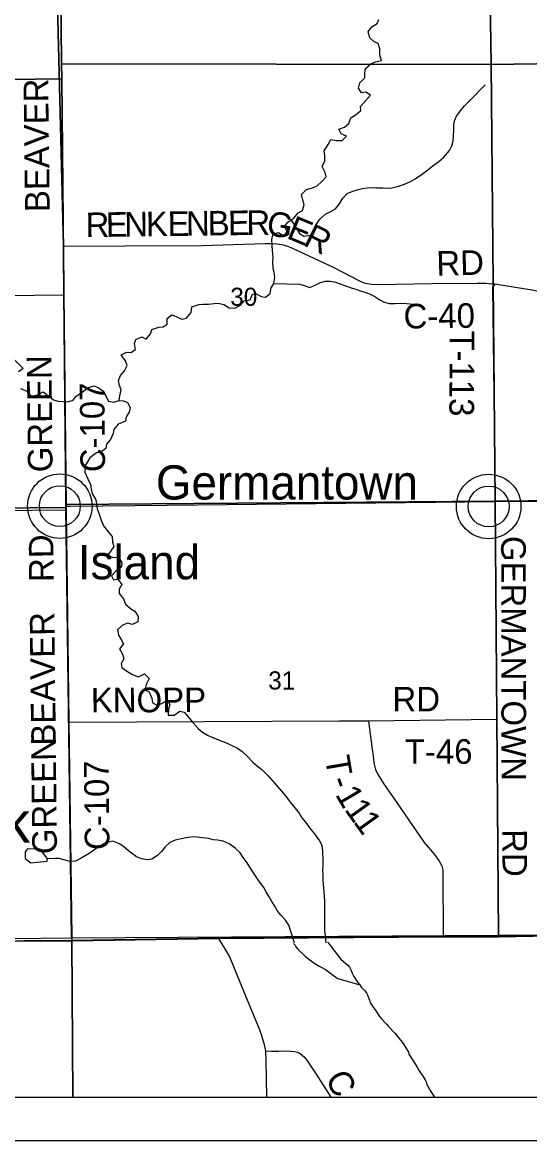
# Model space of a CAD drawing. Extents: x 0 to 36.9, y 0 to 22.
# Drawn here: x 4.148 to 5.318, y 14 to 16.582 of the extents above; entities that cross this region are included whole.
import ezdxf

# ---------------------------------------------------------------- set-up
doc = ezdxf.new("R2010")
doc.units = 0
for name, color, linetype in [('GM_X_County_Road', 7, 'Continuous'), ('GM_X_County_Road_Text', 7, 'Continuous'), ('GM_X_Minor_Lake', 7, 'Continuous'), ('GM_X_Minor_Lake_Text', 7, 'Continuous'), ('GM_X_Minor_River', 7, 'Continuous'), ('GM_X_Rail_Line', 7, 'Continuous'), ('GM_X_Section', 7, 'Continuous'), ('GM_X_Section_Text', 7, 'Continuous'), ('GM_X_State_Route', 7, 'Continuous'), ('GM_X_Township_Road', 7, 'Continuous'), ('GM_X_Township_Road_Text', 7, 'Continuous'), ('GM_X_Unincorporated', 7, 'Continuous'), ('GM_X_Unincorporated_Location', 7, 'Continuous'), ('GM_X_Unincorporated_Text', 7, 'Continuous'), ('SH_Cut_Line', 7, 'Continuous'), ('SH_Data', 7, 'Continuous')]:
    doc.layers.add(name, color=color, linetype=linetype)

msp = doc.modelspace()

# ---------------------------------------------------------------- linework, layer by layer
at = {"layer": 'GM_X_County_Road'}
for p, q in [((3.2939, 15.4488), (4.2488, 15.4562)), ((4.2488, 15.4651), (4.2587, 15.4652)), ((4.2488, 15.4562), (4.2488, 15.4651)), ((4.2552, 14.9656), (4.2488, 15.4562))]:
    msp.add_line(p, q, dxfattribs=at)
for points in [[(4.2488, 15.4651), (4.2434, 15.9526), (4.243, 16.0644), (4.2239, 16.8055), (4.2216, 17.4415)], [(5.2175, 15.9787), (5.197, 15.9789), (5.0925, 15.9784), (4.9679, 15.9763), (4.9529, 15.977), (4.9441, 15.9779), (4.9361, 15.9801), (4.9264, 15.9841), (4.8658, 16.0156), (4.776, 16.0576), (4.7622, 16.0637), (4.7526, 16.0667), (4.7461, 16.0686), (4.7358, 16.0701), (4.7243, 16.0705), (4.7077, 16.0705), (4.5615, 16.0663), (4.3849, 16.0655), (4.243, 16.0644)], [(5.3825, 15.9549), (5.3493, 15.9585), (5.3236, 15.9637), (5.2563, 15.9747), (5.2373, 15.9775), (5.2243, 15.9786), (5.2175, 15.9787)], [(4.2587, 15.4652), (4.4807, 15.4671), (5.2386, 15.4759), (5.5595, 15.4781), (5.5699, 15.4782), (5.5803, 15.4783), (6.0155, 15.4812)], [(4.2622, 14.4614), (4.2621, 14.4708), (4.2552, 14.9656)]]:
    msp.add_lwpolyline(points, dxfattribs=at)
at = {"layer": 'GM_X_Minor_Lake'}
for points in [[(4.1889, 14.6729), (4.1592, 14.6736), (4.1544, 14.667), (4.1539, 14.6511), (4.1669, 14.6411), (4.1817, 14.6428), (4.2049, 14.6451)], [(4.2049, 14.6451), (4.2055, 14.6476), (4.204, 14.6528), (4.1889, 14.6729)]]:
    msp.add_lwpolyline(points, dxfattribs=at)
at = {"layer": 'GM_X_Minor_River'}
for points in [[(4.9626, 16.4908), (4.9759, 16.4937), (4.9726, 16.5069), (4.9724, 16.5206), (4.9687, 16.5331), (4.9591, 16.5371), (4.9495, 16.546), (4.9458, 16.5604), (4.9536, 16.5719), (4.9664, 16.579), (4.97, 16.5889)], [(4.3707, 15.7089), (4.3728, 15.7195), (4.3759, 15.7336), (4.3716, 15.7438), (4.3695, 15.7548), (4.3738, 15.7662), (4.3831, 15.777), (4.3894, 15.7897), (4.3854, 15.8002), (4.3756, 15.8145), (4.3877, 15.8208), (4.3976, 15.8198), (4.4084, 15.8265), (4.4067, 15.8401), (4.4092, 15.85), (4.4231, 15.8556), (4.4331, 15.8508), (4.4431, 15.8624), (4.4463, 15.8731), (4.4622, 15.8783), (4.4721, 15.8788), (4.4818, 15.8851), (4.4816, 15.8984), (4.4928, 15.9065), (4.5024, 15.9025), (4.5154, 15.8967), (4.526, 15.8988), (4.5368, 15.9119), (4.5388, 15.9248), (4.5547, 15.9308), (4.5653, 15.9314), (4.5767, 15.9316), (4.5899, 15.9326), (4.5994, 15.9335), (4.6124, 15.9303), (4.6247, 15.9225), (4.6376, 15.9224), (4.6511, 15.9287), (4.6597, 15.9387), (4.6729, 15.9416), (4.6784, 15.9546), (4.6879, 15.9552), (4.6982, 15.9489), (4.7089, 15.9472), (4.7194, 15.9557), (4.7214, 15.9691), (4.7277, 15.979), (4.7301, 15.9928), (4.7284, 16.0045), (4.7263, 16.0143), (4.7253, 16.0291), (4.7262, 16.0401), (4.7248, 16.0553), (4.7238, 16.0671), (4.7232, 16.0803), (4.726, 16.0933), (4.7385, 16.0969), (4.7519, 16.0884), (4.7586, 16.0992), (4.7523, 16.1108), (4.7601, 16.1208), (4.7736, 16.1298), (4.784, 16.1425), (4.7942, 16.1476), (4.7977, 16.1606), (4.7937, 16.1742), (4.792, 16.1844), (4.8028, 16.196), (4.8171, 16.2001), (4.8281, 16.2044), (4.8393, 16.2149), (4.8482, 16.2249), (4.8465, 16.2355), (4.8394, 16.2491), (4.8453, 16.2621), (4.8458, 16.2746), (4.8441, 16.2852), (4.8533, 16.3002), (4.8592, 16.3113), (4.8717, 16.3092), (4.8858, 16.3091), (4.8951, 16.3195), (4.8832, 16.3243), (4.8777, 16.3352), (4.8909, 16.3403), (4.901, 16.3485), (4.9057, 16.3615), (4.9174, 16.3693), (4.9282, 16.3782), (4.9277, 16.3877), (4.9392, 16.4008), (4.9511, 16.4139), (4.94, 16.4206), (4.9301, 16.4189), (4.9231, 16.4298), (4.9263, 16.442), (4.9379, 16.4536), (4.938, 16.4646), (4.939, 16.4752), (4.9513, 16.4861), (4.9626, 16.4908)], [(4.7679, 16.1261), (4.7868, 16.0944), (4.7971, 16.0881), (4.813, 16.0907), (4.8193, 16.1006), (4.8255, 16.1152), (4.8344, 16.1282), (4.8478, 16.1395), (4.8576, 16.1442), (4.8697, 16.1513), (4.8793, 16.1632), (4.8867, 16.1759), (4.8971, 16.1867), (4.9099, 16.1922), (4.9201, 16.1951), (4.9326, 16.1983), (4.9428, 16.2), (4.9527, 16.201), (4.9633, 16.2), (4.9789, 16.1995), (4.9892, 16.1993), (4.9998, 16.1999), (5.0157, 16.2036), (5.0289, 16.2084), (5.0432, 16.2147), (5.0541, 16.2206), (5.071, 16.2319), (5.0829, 16.2413), (5.0953, 16.2517), (5.1084, 16.2607), (5.1193, 16.2696), (5.133, 16.2858), (5.1385, 16.2965), (5.1414, 16.3084), (5.1423, 16.3201), (5.1428, 16.3331), (5.1434, 16.3445), (5.1447, 16.3544), (5.1494, 16.3651), (5.1602, 16.3797), (5.168, 16.3893), (5.1814, 16.4028), (5.193, 16.4144), (5.2042, 16.426), (5.2153, 16.438)], [(4.7277, 15.979), (4.7877, 15.9775), (4.8003, 15.9735), (4.811, 15.9699), (4.8246, 15.9758), (4.8351, 15.981), (4.8472, 15.9842), (4.8578, 15.9844), (4.87, 15.982), (4.8811, 15.978), (4.893, 15.9736), (4.9063, 15.9689), (4.9167, 15.9657), (4.927, 15.9621), (4.938, 15.9589), (4.9503, 15.9542), (4.961, 15.9487), (4.9725, 15.9413), (4.9825, 15.9361), (4.9936, 15.9329), (5.008, 15.9332), (5.0228, 15.9338), (5.0338, 15.9325), (5.0494, 15.9309)], [(4.1295, 15.8031), (4.1491, 15.7831), (4.1386, 15.775)], [(4.1435, 15.7367), (4.1577, 15.7305), (4.1697, 15.7182), (4.1825, 15.7222), (4.1957, 15.7285), (4.208, 15.7193), (4.2195, 15.7107), (4.2302, 15.7075), (4.2416, 15.7062), (4.2515, 15.7056), (4.2651, 15.7093), (4.2714, 15.7189), (4.2849, 15.7275), (4.2976, 15.7383), (4.3124, 15.7424), (4.3227, 15.7388), (4.3354, 15.7299), (4.3397, 15.7201), (4.346, 15.7077), (4.3586, 15.7052), (4.3707, 15.7089), (4.3806, 15.7079), (4.3905, 15.7043), (4.3964, 15.693), (4.394, 15.682), (4.3873, 15.6708), (4.3852, 15.6609), (4.369, 15.6546), (4.359, 15.6422), (4.3569, 15.6323), (4.351, 15.6189), (4.3417, 15.6081), (4.3404, 15.5979), (4.3284, 15.5893), (4.3186, 15.588), (4.3036, 15.5767), (4.2977, 15.5671), (4.2918, 15.5571), (4.292, 15.5435), (4.2987, 15.528), (4.3047, 15.5149), (4.3064, 15.5043), (4.3088, 15.4941), (4.3171, 15.4798), (4.3184, 15.4696), (4.3205, 15.459), (4.3257, 15.4443), (4.3293, 15.4329), (4.3345, 15.4194), (4.3461, 15.4048), (4.355, 15.3947), (4.3557, 15.3814), (4.3589, 15.3716), (4.3448, 15.3516), (4.3571, 15.3461), (4.3703, 15.3475), (4.3774, 15.3351), (4.3764, 15.3248), (4.3637, 15.3155), (4.3529, 15.3043), (4.358, 15.2945), (4.3678, 15.2966), (4.3772, 15.2839), (4.3709, 15.2731), (4.3707, 15.2636), (4.3812, 15.2509), (4.3859, 15.2388), (4.3971, 15.2284), (4.4071, 15.2221), (4.4149, 15.2101), (4.4144, 15.198), (4.402, 15.1917), (4.3905, 15.1949), (4.3781, 15.1897), (4.3672, 15.1793), (4.3694, 15.1672), (4.3756, 15.157), (4.3807, 15.1469), (4.3715, 15.1353), (4.3789, 15.1233), (4.3821, 15.1124), (4.3758, 15.102), (4.3775, 15.0922), (4.3899, 15.0833), (4.4014, 15.0759), (4.4155, 15.0705), (4.4294, 15.0775), (4.4403, 15.0671), (4.4329, 15.0533), (4.4305, 15.0411), (4.4404, 15.036), (4.446, 15.0217), (4.4481, 15.0107), (4.46, 15.0048), (4.4705, 15.0099), (4.4822, 15.017)], [(4.4822, 15.017), (4.4877, 15.0068), (4.4848, 14.9962), (4.4843, 14.9821), (4.498, 14.9824), (4.5111, 14.9913), (4.521, 14.9892), (4.5299, 14.9784), (4.542, 14.9645), (4.5536, 14.9518), (4.5632, 14.9433), (4.5751, 14.9359), (4.5847, 14.9315), (4.6099, 14.9213), (4.6199, 14.9177), (4.6295, 14.913), (4.644, 14.9064), (4.6548, 14.8986), (4.6671, 14.8871), (4.6791, 14.8736), (4.6899, 14.8643), (4.7003, 14.8569), (4.715, 14.8424), (4.7255, 14.83), (4.736, 14.8173), (4.7456, 14.8068), (4.758, 14.7923), (4.7651, 14.7821), (4.7728, 14.7724), (4.7864, 14.7563), (4.7927, 14.7454), (4.8012, 14.735), (4.8098, 14.7222), (4.8214, 14.708), (4.8331, 14.6923), (4.8382, 14.6825), (4.8404, 14.6692), (4.8408, 14.6461), (4.8406, 14.6362), (4.8404, 14.6244), (4.8406, 14.6134), (4.8412, 14.6021), (4.8414, 14.5918), (4.8428, 14.5755), (4.8438, 14.5634), (4.8444, 14.552), (4.8446, 14.538), (4.8444, 14.5281), (4.8448, 14.5061), (4.8446, 14.4951), (4.8444, 14.4852), (4.8476, 14.4565)], [(4.7755, 14.4567), (4.7626, 14.4974), (4.7544, 14.5087), (4.7439, 14.5202), (4.7358, 14.5311), (4.7303, 14.5413), (4.7232, 14.5525), (4.717, 14.5627), (4.7103, 14.5743), (4.7044, 14.5841), (4.6951, 14.5976), (4.6869, 14.6092), (4.6791, 14.6204), (4.6724, 14.6313), (4.6666, 14.6411), (4.6572, 14.6534), (4.6498, 14.6647), (4.6386, 14.6751), (4.6248, 14.6851), (4.611, 14.6913), (4.5981, 14.6934), (4.5878, 14.6947), (4.5767, 14.6972), (4.563, 14.6992), (4.5512, 14.7009), (4.5417, 14.7011), (4.5315, 14.7002), (4.5209, 14.6985), (4.5111, 14.696), (4.5005, 14.6935), (4.488, 14.6884), (4.4768, 14.6783), (4.4687, 14.6679), (4.4593, 14.6583), (4.4462, 14.6501), (4.4352, 14.6487), (4.4226, 14.6508), (4.4108, 14.6555), (4.3965, 14.6659), (4.3823, 14.6774), (4.3719, 14.6852), (4.3562, 14.6914), (4.3403, 14.6877), (4.3306, 14.6822), (4.3204, 14.6759), (4.3084, 14.6674), (4.2979, 14.6603), (4.2836, 14.6525), (4.2705, 14.6454), (4.2568, 14.6441), (4.2461, 14.6473), (4.2328, 14.6516), (4.2233, 14.6514), (4.2047, 14.6503)], [(4.7734, 14.4555), (4.7769, 14.4516), (4.7788, 14.4471), (4.7835, 14.4422), (4.7998, 14.4258), (4.8082, 14.4191), (4.8136, 14.415), (4.8221, 14.4091), (4.8325, 14.4032), (4.8371, 14.4002), (4.8471, 14.3951), (4.8521, 14.391), (4.8571, 14.3877), (4.8706, 14.3777), (4.8752, 14.3743), (4.926, 14.3601)], [(4.8513, 14.4585), (4.8601, 14.4482), (4.8675, 14.4377), (4.8718, 14.4325), (4.8827, 14.4186), (4.8889, 14.4134), (4.8982, 14.4052), (4.9024, 14.4007), (4.906, 14.3928), (4.9088, 14.3864), (4.9127, 14.3788), (4.9206, 14.366), (4.926, 14.3601), (4.9303, 14.3533), (4.9369, 14.3469), (4.9419, 14.3413), (4.9439, 14.3364), (4.9463, 14.3296), (4.9483, 14.3247), (4.9504, 14.3183), (4.9593, 14.3051), (4.9629, 14.2995), (4.9719, 14.2867), (4.9754, 14.2822), (4.9874, 14.2691), (4.992, 14.2639), (5.0068, 14.2478), (5.0239, 14.2276), (5.0274, 14.2219), (5.0388, 14.2043), (5.0396, 14.1997), (5.0478, 14.1869), (5.0506, 14.182), (5.0588, 14.1693), (5.062, 14.1629), (5.0678, 14.1546), (5.0706, 14.1501), (5.0768, 14.1407), (5.0796, 14.1358), (5.0804, 14.1312), (5.0903, 14.1135), (5.0984, 14.1)]]:
    msp.add_lwpolyline(points, dxfattribs=at)
at = {"layer": 'GM_X_Rail_Line'}
for points in [[(3.4854, 14.4568), (4.262, 14.4619), (4.2619, 14.4713), (4.255, 14.9661), (4.2486, 15.4567), (4.2486, 15.4657), (4.2432, 15.9532), (4.2428, 16.065), (4.2237, 16.806)], [(4.2237, 16.806), (4.2428, 16.065), (4.2432, 15.9532), (4.2486, 15.4657), (4.2486, 15.4567), (4.255, 14.9661), (4.2619, 14.4713), (4.262, 14.4619), (4.6008, 14.4672), (5.1185, 14.4712), (5.2462, 14.4712), (5.4467, 14.4748)], [(2.1, 14.1), (4.2643, 14.1), (4.262, 14.4619), (3.4854, 14.4568)]]:
    msp.add_lwpolyline(points, dxfattribs=at)
msp.add_lwpolyline([(4.2643, 14.1), (8.9, 14.1), (8.9, 14.5158), (8.6137, 14.5116), (7.9858, 14.497), (7.7356, 14.4946), (7.4027, 14.4935), (7.1313, 14.488), (6.8569, 14.4852), (6.7812, 14.4863), (6.7336, 14.4854), (6.5807, 14.485), (6.4063, 14.4846), (5.9207, 14.4754), (5.4676, 14.4751), (5.4581, 14.475), (5.4467, 14.4748), (5.2462, 14.4712), (5.1185, 14.4712), (4.6008, 14.4672), (4.262, 14.4619)], close=True, dxfattribs=at)
at = {"layer": 'GM_X_Section'}
for points in [[(6.2201, 17.5106), (6.226, 16.4996), (5.2292, 16.4845), (5.2141, 17.498)], [(5.2141, 17.498), (5.2292, 16.4845), (4.2381, 16.4858), (4.2298, 17.4444), (4.2298, 17.4831)], [(4.2298, 17.4444), (4.2381, 16.4858), (4.2388, 16.4513), (3.2483, 16.4396), (3.2373, 17.4365)], [(5.2292, 16.4845), (6.226, 16.4996), (6.2395, 15.4861), (5.2381, 15.4765)], [(4.2381, 16.4858), (5.2292, 16.4845), (5.2381, 15.4765), (4.2479, 15.4684), (4.2388, 16.4513)], [(4.2388, 16.4513), (4.2479, 15.4684), (4.2477, 15.4619), (3.2569, 15.4522), (3.2483, 16.4396)], [(4.2479, 15.4684), (5.2381, 15.4765), (5.2461, 14.474), (4.2613, 14.4673), (4.2477, 15.4619)], [(5.2381, 15.4765), (6.2395, 15.4861), (6.2525, 14.4815), (5.2461, 14.474)], [(4.2477, 15.4619), (4.2613, 14.4673), (3.2645, 14.457), (3.2569, 15.4522)]]:
    msp.add_lwpolyline(points, close=True, dxfattribs=at)
at = {"layer": 'GM_X_State_Route'}
msp.add_line((3.6051, 14.4571), (4.2522, 14.4613), dxfattribs=at)
for points in [[(4.2522, 14.4613), (4.2622, 14.4614), (4.601, 14.4666)], [(4.601, 14.4666), (5.1187, 14.4707), (5.2464, 14.4707), (5.4469, 14.4743), (5.4583, 14.4745), (5.4678, 14.4745), (5.8599, 14.4748)]]:
    msp.add_lwpolyline(points, dxfattribs=at)
at = {"layer": 'GM_X_Township_Road'}
for points in [[(3.255, 15.8649), (3.2722, 15.8709), (3.4495, 15.9507), (3.4891, 15.9696), (3.4985, 15.9733), (3.5054, 15.9754), (3.5127, 15.9763), (3.5199, 15.9761), (3.5279, 15.9747), (3.563, 15.9647), (3.6105, 15.9505), (3.6182, 15.9487), (3.625, 15.9472), (3.6361, 15.946), (4.2434, 15.9526)], [(5.2373, 15.9775), (5.2343, 15.9738), (5.2325, 15.9696), (5.2386, 15.4759)], [(5.2386, 15.4759), (5.2422, 14.9723), (5.2464, 14.4707)], [(5.2422, 14.9723), (4.9462, 14.9685), (4.8796, 14.9685), (4.2552, 14.9656)], [(4.9462, 14.9685), (4.955, 14.9036), (4.9566, 14.8883), (4.9582, 14.8724), (4.9621, 14.8567), (4.9673, 14.8468), (4.982, 14.8226), (5.004, 14.7914), (5.0747, 14.6886), (5.0986, 14.6603), (5.1088, 14.6465), (5.1127, 14.6399), (5.1152, 14.6342), (5.117, 14.6287), (5.1174, 14.624), (5.1176, 14.6185), (5.1187, 14.4707)], [(4.712, 14.1), (4.7104, 14.1859), (4.7093, 14.2077), (4.7063, 14.2213), (4.6998, 14.2423), (4.6946, 14.2576), (4.6595, 14.3431), (4.6257, 14.426), (4.601, 14.4666)], [(4.7093, 14.2077), (4.7228, 14.2066), (4.7395, 14.2065), (4.76, 14.2071), (4.7662, 14.2067), (4.7761, 14.206), (4.7822, 14.2041), (4.7888, 14.2011), (4.7935, 14.1974), (4.7983, 14.1926), (4.8054, 14.1833), (4.8242, 14.1557), (4.8593, 14.1)]]:
    msp.add_lwpolyline(points, dxfattribs=at)
at = {"layer": 'GM_X_Unincorporated'}
for centre, radius in [((4.2341, 15.4649), 0.0744), ((5.2235, 15.4642), 0.0744), ((4.2341, 15.4649), 0.0472), ((5.2235, 15.4642), 0.0472)]:
    msp.add_circle(centre, radius, dxfattribs=at)
at = {"layer": 'GM_X_Unincorporated_Location'}
for p, q in [((4.2341, 15.4649), (4.2341, 15.4649)), ((5.2235, 15.4642), (5.2235, 15.4642))]:
    msp.add_line(p, q, dxfattribs=at)
at = {"layer": 'SH_Cut_Line'}
for points in [[(3.4854, 14.4568), (4.262, 14.4619), (4.6008, 14.4672), (5.1185, 14.4712), (5.2462, 14.4712), (5.4467, 14.4748)], [(5.4467, 14.4748), (5.2462, 14.4712), (5.1185, 14.4712), (4.6008, 14.4672), (4.262, 14.4619), (3.4854, 14.4568)], [(2.1, 14.1), (8.9, 14.1)]]:
    msp.add_lwpolyline(points, dxfattribs=at)
at = {"layer": 'SH_Data'}
for p, q in [((2.1, 14.1), (8.9, 14.1)), ((2, 14), (9, 14))]:
    msp.add_line(p, q, dxfattribs=at)

# ---------------------------------------------------------------- texts
at = {"layer": 'GM_X_County_Road_Text'}
for s, height, rotation, p in [('BEAVER', 0.05682, 90.6885, (4.2108, 16.1442)), ('R', 0.0568, 0.7533, (4.2939, 16.0859)), ('E', 0.0568, 0.7522, (4.3405, 16.0866)), ('N', 0.0568, 0.7538, (4.383, 16.0871)), ('K', 0.0568, 0.7523, (4.433, 16.0878)), ('E', 0.0568, 0.7541, (4.483, 16.0884)), ('N', 0.0568, 0.7523, (4.5255, 16.089)), ('B', 0.0568, 0.7524, (4.5755, 16.0897)), ('E', 0.0568, 0.7543, (4.6222, 16.0903)), ('R', 0.0568, 0.3239, (4.6646, 16.0908)), ('G', 0.0568, 351.0683, (4.7088, 16.0913)), ('E', 0.0568, 337.4593, (4.7548, 16.0845)), ('R', 0.0568, 333.4646, (4.7931, 16.0686)), ('RD', 0.05682, 1.4255, (5.1034, 15.9968)), ('C-40', 0.05682, 0.6882, (5.0274, 15.8749)), ('GREEN', 0.05682, 90.6179, (4.2175, 15.5434)), ('C-107', 0.05682, 90.5506, (4.3386, 15.5437)), ('RD', 0.05682, 90.4955, (4.22, 15.2901)), ('BEAVER', 0.05682, 90.6887, (4.225, 14.9123)), ('GREEN', 0.05682, 90.6179, (4.2275, 14.6617)), ('C-107', 0.05682, 90.5506, (4.3486, 14.6712))]:
    msp.add_text(s, height=height, rotation=rotation, dxfattribs=at).set_placement(p)
at = {"layer": 'GM_X_Minor_Lake_Text'}
msp.add_text('Liberty Park', height=0.094726, rotation=359.9543, dxfattribs=at).set_placement((3.4895, 14.6882))
at = {"layer": 'GM_X_Section_Text'}
for s, p in [('30', (4.6274, 15.9274)), ('31', (4.7149, 15.0416))]:
    msp.add_text(s, height=0.04186, rotation=0, dxfattribs=at).set_placement(p)
at = {"layer": 'GM_X_Township_Road_Text'}
for s, height, rotation, p in [('T-113', 0.05682, 269.7193, (5.1337, 15.8707)), ('GERMANTOWN', 0.05682, 270.0937, (5.2522, 15.3961)), ('KNOPP', 0.05682, 0.2098, (4.3056, 14.9885)), ('RD', 0.05682, 0, (5.0015, 14.9909)), ('T-46', 0.05682, 0, (5.0299, 14.87)), ('T', 0.0568, 279.6751, (4.8455, 14.8841)), ('-', 0.0568, 290.0961, (4.8555, 14.8314)), ('1', 0.0568, 300.5171, (4.8683, 14.7993)), ('1', 0.0568, 305.7276, (4.8892, 14.7644)), ('1', 0.0568, 305.7276, (4.9096, 14.736)), ('RD', 0.05682, 270.4937, (5.2547, 14.7188)), ('C', 0.0568, 299.4079, (4.845, 14.1428))]:
    msp.add_text(s, height=height, rotation=rotation, dxfattribs=at).set_placement(p)
at = {"layer": 'GM_X_Unincorporated_Text'}
for s, p in [('Germantown', (4.4557, 15.4802)), ('Island', (4.2757, 15.2961))]:
    msp.add_text(s, height=0.07898, rotation=0, dxfattribs=at).set_placement(p)

doc.saveas('drawing.dxf')
